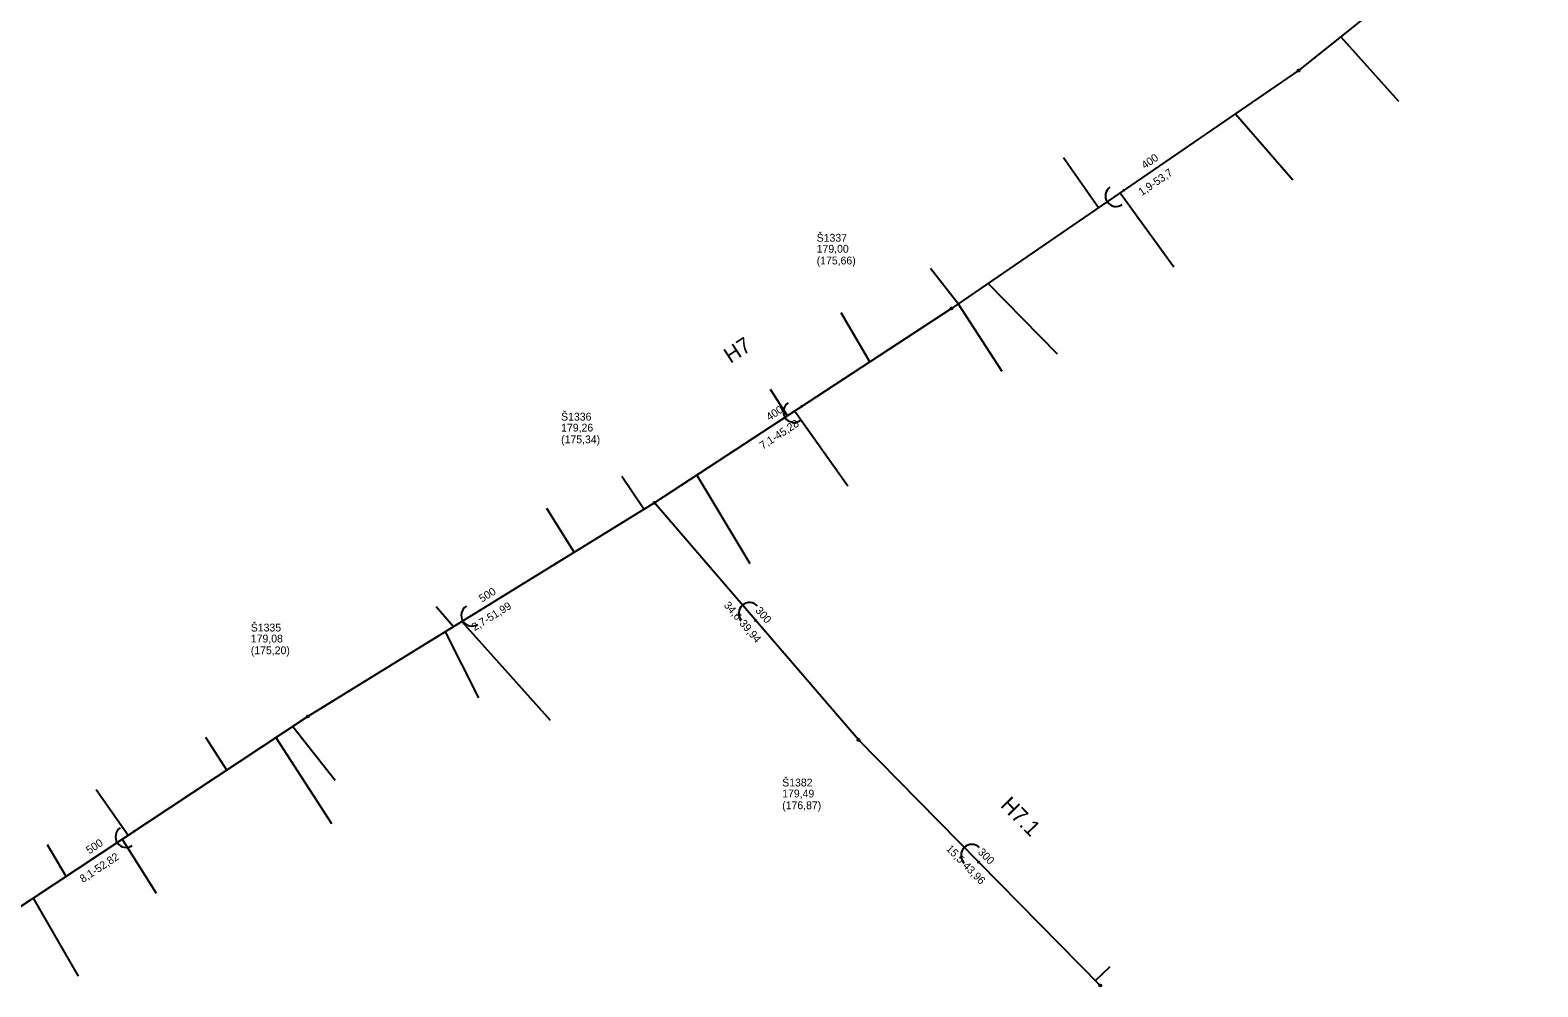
# Model space of a CAD drawing. Extents: x -548529 to -543591, y -1201432 to -1192608.
# Drawn here: x -546034.2 to -545841.7, y -1194675.3 to -1194553.3 of the extents above; entities that cross this region are included whole.
import ezdxf

# ---------------------------------------------------------------- set-up
doc = ezdxf.new("R2010")
doc.units = 0
for name, color, linetype in [('C3D_Bod-Značky', 7, 'Continuous'), ('C3D_Koridor', 7, 'Continuous'), ('C3D_Křižovatka', 7, 'Continuous'), ('C3D_Netisknutelná', 7, 'Continuous'), ('C3D_PP-zobrazeni v PR', 7, 'Continuous'), ('C3D_PR-Popisek', 7, 'Continuous'), ('C3D_SPR-Popisek', 7, 'Continuous'), ('C3D_Tlakove_potrubi_Popis', 7, 'Continuous'), ('C3D_ZPR-Formaty', 7, 'Continuous')]:
    doc.layers.add(name, color=color, linetype=linetype)

# ---------------------------------------------------------------- blocks, each defined once
blk = doc.blocks.new('100')
at = {"layer": 'Defpoints'}
blk.add_circle((0, 0), 0.127, dxfattribs=at)
blk = doc.blocks.new('91')
at = {"layer": 'Defpoints'}
blk.add_lwpolyline([(0.08, 0.14), (0.19, 0), (0.08, -0.14)], dxfattribs=at)
blk.add_arc((1.37, 0), 1.37, 270, 90, dxfattribs=at)
blk = doc.blocks.new('86')
at = {"layer": 'Defpoints'}
blk.add_lwpolyline([(0.08, 0.14), (0.19, 0), (0.08, -0.14)], dxfattribs=at)
blk.add_arc((1.37, 0), 1.37, 270, 90, dxfattribs=at)

msp = doc.modelspace()

# ---------------------------------------------------------------- linework, layer by layer
at = {"layer": 'C3D_Bod-Značky'}
for points in [[(-545841.741, -1194534.002), (-545872.298, -1194558.435)], [(-545872.298, -1194558.435), (-545916.589, -1194588.804)], [(-545916.589, -1194588.804), (-545954.49, -1194613.58)], [(-545954.49, -1194613.58), (-545998.747, -1194640.865)], [(-545928.44, -1194643.85), (-545954.49, -1194613.58)], [(-545998.747, -1194640.865), (-546042.816, -1194669.99)], [(-545897.59, -1194675.17), (-545928.44, -1194643.85)]]:
    msp.add_lwpolyline(points, dxfattribs=at)
at = {"layer": 'C3D_Koridor'}
for points in [[(-545866.893, -1194554.113), (-545859.539, -1194562.348)], [(-545880.348, -1194563.954), (-545873.017, -1194572.363)], [(-545897.84, -1194575.949), (-545902.27, -1194569.576)], [(-545895.036, -1194574.026), (-545888.19, -1194583.491)], [(-545915.712, -1194588.203), (-545919.276, -1194583.663)], [(-545911.893, -1194585.584), (-545903.112, -1194594.59)], [(-545915.712, -1194588.203), (-545910.163, -1194596.764)], [(-545927.004, -1194595.612), (-545930.658, -1194589.349)], [(-545937.507, -1194602.478), (-545939.704, -1194599.137)], [(-545936.595, -1194601.882), (-545929.797, -1194611.435)], [(-545955.855, -1194614.414), (-545958.67, -1194610.244)], [(-545949.083, -1194610.062), (-545942.311, -1194621.324)], [(-545964.73, -1194619.893), (-545968.241, -1194614.309)], [(-545980.135, -1194629.391), (-545982.377, -1194626.878)], [(-545979.088, -1194628.732), (-545967.797, -1194641.31)], [(-545981.222, -1194630.061), (-545976.941, -1194638.463)], [(-546000.666, -1194642.133), (-545995.254, -1194648.974)], [(-546009.069, -1194647.687), (-546011.763, -1194643.534)], [(-546002.809, -1194643.55), (-545995.74, -1194654.502)], [(-546021.686, -1194656.026), (-546025.746, -1194650.206)], [(-546029.598, -1194661.254), (-546031.969, -1194657.22)], [(-546022.433, -1194656.519), (-546018.09, -1194663.402)], [(-546033.81, -1194664.038), (-546028.051, -1194673.995)], [(-545898.197, -1194674.554), (-545896.31, -1194672.76)]]:
    msp.add_lwpolyline(points, dxfattribs=at)

# ---------------------------------------------------------------- block references
at = {"layer": 'C3D_PP-zobrazeni v PR'}
for p, xscale, yscale, rotation in [((-545872.298, -1194558.435), 0.9999999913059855, 0.9999999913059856, -142.99999806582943), ((-545916.589, -1194588.804), 0.9999999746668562, 0.999999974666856, 34.00000045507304), ((-545954.49, -1194613.58), 0.9999999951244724, 0.9999999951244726, 33.000001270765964), ((-545998.747, -1194640.865), 0.9999999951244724, 0.9999999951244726, 33.000001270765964), ((-545928.44, -1194643.85), 1.00000000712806, 1.00000000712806, -46.99999943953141), ((-545897.59, -1194675.17), 0.999999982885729, 0.9999999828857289, -45)]:
    msp.add_blockref('100', p, dxfattribs=dict(at, xscale=xscale, yscale=yscale, rotation=rotation))
at = {"layer": 'C3D_SPR-Popisek'}
for name, p, xscale, yscale, rotation in [('91', (-545894.444, -1194573.62), 1.000000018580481, 1.000000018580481, -144.99999976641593), ('91', (-545935.54, -1194601.192), 0.9999999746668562, 0.999999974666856, -145.99999954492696), ('91', (-545976.618, -1194627.223), 0.9999999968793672, 0.9999999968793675, -147.99999972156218), ('86', (-545941.465, -1194628.715), 1.0000000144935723, 1.0000000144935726, 130.99999910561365), ('91', (-546020.782, -1194655.428), 0.9999999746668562, 0.999999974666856, -145.99999954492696), ('86', (-545913.015, -1194659.51), 0.999999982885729, 0.9999999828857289, 135)]:
    msp.add_blockref(name, p, dxfattribs=dict(at, xscale=xscale, yscale=yscale, rotation=rotation))

# ---------------------------------------------------------------- texts
at = {"layer": 'C3D_Křižovatka'}
for s, p in [('Š1337', (-545933.789, -1194580.264)), ('Š1336', (-545966.41, -1194603.09)), ('Š1335', (-546006.017, -1194630.005)), ('Š1382', (-545938.19, -1194649.78))]:
    msp.add_text(s, height=1, dxfattribs=at).set_placement(p)
at = {"layer": 'C3D_Netisknutelná'}
for s, rotation, p in [('H7', 33.17, (-545944.8, -1194595.863)), ('H7.1', 314.57, (-545910.444, -1194652.29))]:
    msp.add_text(s, height=2, rotation=rotation, dxfattribs=at).set_placement(p)
at = {"layer": 'C3D_PR-Popisek'}
for s, rotation, p in [('400', 34.44, (-545891.91, -1194571.039)), ('400', 33.17, (-545939.823, -1194603.157)), ('500', 31.65, (-545976.523, -1194626.338)), ('300', 310.71, (-545941.685, -1194627.381)), ('500', 33.46, (-546026.638, -1194658.453)), ('300', 314.57, (-545913.284, -1194658.236))]:
    msp.add_text(s, height=1, rotation=rotation, dxfattribs=at).set_placement(p)
at = {"layer": 'C3D_Tlakove_potrubi_Popis'}
for s, p in [('179,00 ', (-545933.789, -1194581.664)), ('(175,66)', (-545933.789, -1194583.164)), ('179,26 ', (-545966.41, -1194604.49)), ('(175,34)', (-545966.41, -1194605.99)), ('179,08 ', (-546006.017, -1194631.405)), ('(175,20)', (-546006.017, -1194632.905)), ('179,49 ', (-545938.19, -1194651.18)), ('(176,87)', (-545938.19, -1194652.68))]:
    msp.add_text(s, height=1, dxfattribs=at).set_placement(p)
at = {"layer": 'C3D_ZPR-Formaty'}
for s, rotation, p in [('1,9-53,7', 34.44, (-545892.294, -1194574.456)), ('7,1-45,28', 33.17, (-545940.668, -1194606.806)), ('2,7-51,99', 31.65, (-545977.457, -1194629.977)), ('34,6-39,94', 310.71, (-545945.711, -1194626.697)), ('15,5-43,96', 314.57, (-545917.352, -1194657.814)), ('8,1-52,82', 33.46, (-546027.448, -1194662.11))]:
    msp.add_text(s, height=1, rotation=rotation, dxfattribs=at).set_placement(p)

doc.saveas('drawing.dxf')
